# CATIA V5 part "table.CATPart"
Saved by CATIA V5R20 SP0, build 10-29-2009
Part number: 1
Bounding box of the stored display mesh (mm): x -150 to 150, y -100 to 150, z -40 to 20
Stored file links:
  C:\Users\halimelbaba\Documents\cmv\projet\table.CATPart
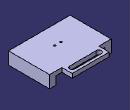
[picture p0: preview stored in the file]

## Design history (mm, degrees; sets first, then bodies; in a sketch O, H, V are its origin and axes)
Body1 (main body)
  Sketch1 on xy-plane, origin (0, 0, 0), H (1, 0, 0), V (0, 1, 0)
    line L1 (-150, 100) -> (150, 100)
    line L2 (150, 100) -> (150, -100)
    line L3 (150, -100) -> (-150, -100)
    line L4 (-150, -100) -> (-150, 100)
    distance L4 L2 = 300
    distance L3 L1 = 200
    horizontal: L1 H, L3 H
    vertical: L2 V, L4 V
    symmetry: L4 L2 V, L1 L3 H
  Pad1: profile Sketch1, direction (0, 0, 1), length 20
  Plane1: type Offset, RefPlane face of Pad1 from Sketch1.L1, Offset 0, reversed
  Sketch2 on Plane1, origin (0, 100, 0), H (1, 0, 0), V (0, 0, 1)
    line L1 (-90, 20) -> (90, 20)
    line L2 (90, 20) -> (90, 0)
    line L3 (90, 0) -> (-90, 0)
    line L4 (-90, 0) -> (-90, 20)
    point P3 (90, 0)
    reference projected line E1 (-100, 20) -> (100, 20) from edge [face of Pad1 from Sketch1.L3 | end face of Pad1]
    distance L2 L4 = 180
    horizontal: L1 H, L3 H
    vertical: L2 V, L4 V
    coincidence: P3 H, L1 E1
    symmetry: L2 L4 V
  Pad2: profile Sketch2, direction (0, 1, 0), length 50
  Sketch3 on face of Pad2, origin (0, 0, 20), H (1, 0, 0), V (0, 1, 0)
    arc A1 centre (65, 125) radius 12.5 from (65, 112.5) to (65, 137.5) ccw
    point P1 (65, 125)
    reference projected line E1 (90, 100) -> (90, 150) from edge [face of Pad2 from Sketch2.L2 | face of Pad2]
    reference projected line E2 (65, 150) -> (-65, 150) from edge [end face of Pad2 | face of Pad2 from Sketch2.L1]
    arc A2 centre (-65, 125) radius 12.5 from (-65, 112.5) to (-65, 137.5) cw
    line L1 (-65, 137.5) -> (65, 137.5)
    line L2 (-65, 112.5) -> (65, 112.5)
    distance P1 E1 = 25
    distance P1 E2 = 25
    radius A1 = 12.5
    symmetry: A1 A2 V
    tangency: L1 A1, L2 A1, L1 A2, L2 A2
  Pocket1: profile Sketch3, direction (0, 0, -1), up to face of Pad2
  Plane2: type Offset, RefPlane face of Pad2, Offset 0, reversed
  Sketch4 on face of Pad2, origin (0, 0, 0), H (1, 0, 0), V (0, -1, 0)
    point P1 (120, 100)
    line L1 (120, 100) -> (150, 100)
    line L2 (150, 100) -> (150, -100)
    line L3 (150, -100) -> (120, -100)
    line L4 (120, -100) -> (120, 100)
    point P2 (150, 100)
    point P3 (150, -100)
    point P4 (120, -100)
    reference projected line E1 (100, -100) -> (-100, -100) from edge [face of Pad2 | face of Pad1 from Sketch1.L1]
    reference projected line E2 (150, 100) -> (150, -100) from edge [start face of Pad1 | face of Pad1 from Sketch1.L2]
    reference projected line E3 (-100, 100) -> (100, 100) from edge [start face of Pad1 | face of Pad1 from Sketch1.L3]
    point P5 (-120, 100)
    point P6 (-120, -100)
    line L5 (-120, -100) -> (-120, 100)
    point P7 (-150, 100)
    point P8 (-120, 100)
    line L6 (-120, 100) -> (-150, 100)
    point P9 (-150, -100)
    point P10 (-150, 100)
    line L7 (-150, 100) -> (-150, -100)
    point P11 (-120, -100)
    point P12 (-150, -100)
    line L8 (-150, -100) -> (-120, -100)
    distance L4 L2 = 30
    horizontal: L1 H, L3 H
    vertical: L2 V, L4 V
    coincidence: L3 E1, L2 E2, L1 E3, P5 P8, P6 P11, P7 P10, P9 P12
    symmetry: P1 P5 V, P4 P6 V, L4 L5 V, P2 P7 V, P1 P8 V, L1 L6 V, P3 P9 V, P2 P10 V, L2 L7 V, P4 P11 V, P3 P12 V, L3 L8 V
  Pad3: profile Sketch4, direction (0, 0, -1), length 40
  Sketch5 on face of Pad2, origin (-15.4079, -6.7164, 20), H (1, 0, 0), V (0, 1, 0)
    point P1 (30.4079, -3.2836)
    reference projected line E1 (165.4079, -93.2836) -> (165.4079, 106.7164) from edge [face of Pad3 | face of Pad2]
    reference projected line E2 (-84.5921, -93.2836) -> (115.4079, -93.2836) from edge [face of Pad3 | face of Pad2]
    distance P1 E1 = 135
    distance P1 E2 = 90
  Hole1: placed by Sketch5, at (15, -10, 20) direction (0, 0, -1), diameter 10, up to face of Pad2
  Sketch6 on face of Pad2, origin (-56.906, -17.2631, 20), H (1, 0, 0), V (0, 1, 0)
    point P1 (41.906, 7.2631)
    reference projected line E1 (-43.094, -82.7369) -> (156.906, -82.7369) from edge [face of Pad3 | face of Pad2]
    reference projected point E2 (71.906, 7.2631) from axis of face of Hole1
    distance P1 E1 = 90
    distance P1 E2 = 30
  Hole2: placed by Sketch6, at (-15, -10, 20) direction (0, 0, -1), diameter 10, up to face of Pad2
